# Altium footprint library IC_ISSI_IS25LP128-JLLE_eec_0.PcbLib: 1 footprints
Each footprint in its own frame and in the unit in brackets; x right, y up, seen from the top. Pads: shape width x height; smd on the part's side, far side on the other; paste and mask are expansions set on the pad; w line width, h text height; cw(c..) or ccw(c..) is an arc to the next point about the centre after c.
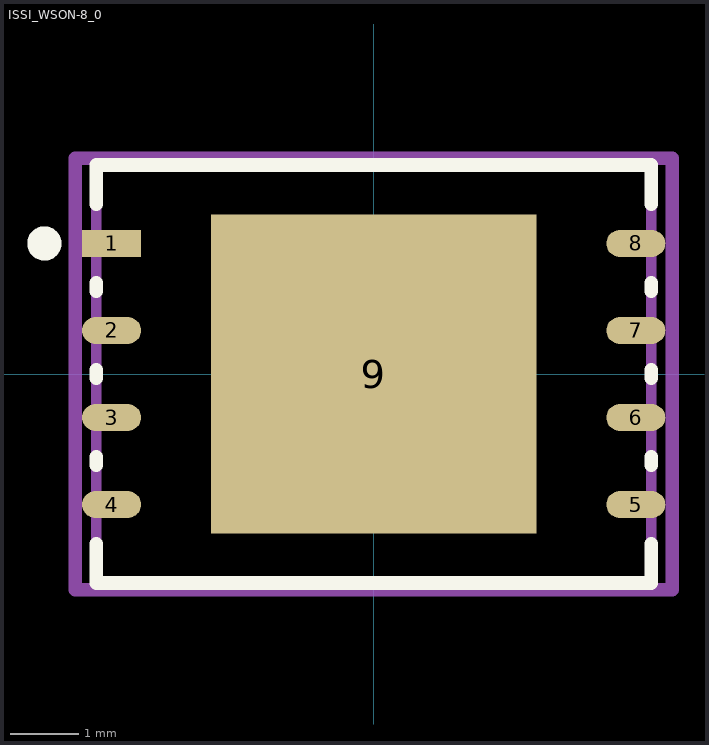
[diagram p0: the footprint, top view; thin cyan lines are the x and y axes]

## ISSI_WSON-8_0 [mm]
pads (9):
  rect 0.861x0.392 smd paste+0 mask+0: 1(-3.826,1.905)
  oval 0.861x0.392 smd paste+0 mask+0: 2(-3.826,0.635) 3(-3.826,-0.635) 4(-3.826,-1.905) 5(3.826,-1.905) 6(3.826,-0.635) 7(3.826,0.635) 8(3.826,1.905)
  rect 4.75x4.65 smd paste-1000 mask+0: 9(0,0)
Top Overlay:
  circle w0.25: c-4.806,1.905 r0.125
  lines w0.2: -4.05,-2.476 -4.05,-3.05 4.05,-3.05 4.05,-2.476 ; -4.05,-1.334 -4.05,-1.206 ; -4.05,-0.064 -4.05,0.064 ; -4.05,1.206 -4.05,1.334 ; -4.05,2.476 -4.05,3.05 4.05,3.05 4.05,2.476 ; 4.05,-1.334 4.05,-1.206 ; 4.05,-0.064 4.05,0.064 ; 4.05,1.206 4.05,1.334
Top Paste:
  rectangle: -1.799,0.288 -0.288,1.749
  rectangle: 0.288,0.288 1.799,1.749
  rectangle: -1.799,-1.749 -0.288,-0.288
  rectangle: 0.288,-1.749 1.799,-0.288
Mechanical 10:
  lines w0.2: -4.356,-3.15 4.356,-3.15 4.356,3.15 -4.356,3.15 -4.356,-3.15
  text ".Designator" at 0,0 h1
Mechanical 12:
  lines w0.15: -4.05,-3.05 4.05,-3.05 4.05,3.05 -4.05,3.05 -4.05,-3.05
Mechanical 15:
  lines w0.1: -0.5,0 0.5,0 ; 0,-0.5 0,0.5
  lines w0.2: -4.356,-3.15 4.356,-3.15 4.356,3.15 -4.356,3.15 -4.356,-3.15
3D body "IC_ISSI_IS25LP128-JLLE_eec.STEP": height 0.25, standoff 0, extent -4.356,-3.15 4.356,3.15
